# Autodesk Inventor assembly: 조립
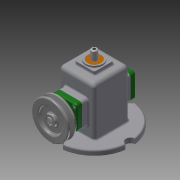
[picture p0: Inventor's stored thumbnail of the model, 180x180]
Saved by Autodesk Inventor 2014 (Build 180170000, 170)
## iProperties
Created: 2018-07
Part Number: 조립
Document SubType Name: Assembly
Designer: kh
Author: kh
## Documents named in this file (16)
- C:\Users\kh\Desktop\480707V1023\조립.iam
- C:\Users\kh\Desktop\480707V1023\본체.ipt
- C:\Users\kh\Desktop\480707V1023\V벨트풀리.ipt
- C:\Users\kh\Desktop\480707V1023\고정핀 1.2x8.ipt
- C:\Users\kh\Desktop\480707V1023\뒤커버.ipt
- C:\Users\kh\Desktop\480707V1023\링크.ipt
- C:\Users\kh\Desktop\480707V1023\멈춤나사 M3x8.ipt
- C:\Users\kh\Desktop\480707V1023\베어링 12x32x10.ipt
- C:\Users\kh\Desktop\480707V1023\볼트 M4.ipt
- C:\Users\kh\Desktop\480707V1023\부시.ipt
- C:\Users\kh\Desktop\480707V1023\슬라이드.ipt
- C:\Users\kh\Desktop\480707V1023\앞커버.ipt
- C:\Users\kh\Desktop\480707V1023\오일 실 12 25 7.ipt
- C:\Users\kh\Desktop\480707V1023\키 4x4x10.ipt
- C:\Users\kh\Desktop\480707V1023\편심축.ipt
- C:\Users\kh\Desktop\480707V1023\핀 5x18.ipt
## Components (3 placed, 3 different names)
1. V벨트풀리:1 — Mate:21, Mate:25, Flush:1, Mate:26, Angle:1
2. 핀 5x18:1 — Mate:9, Mate:10, Mate:11, Mate:12
3. 고정핀 1.2x8:2 — Mate:12, Flush:2
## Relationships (10: Mate 7, Flush 2, Angle 1)
- Mate:9: 핀 5x18:1
- Mate:10: 핀 5x18:1
- Mate:11: 핀 5x18:1
- Mate:12: 핀 5x18:1 ↔ 고정핀 1.2x8:2
- Mate:21: V벨트풀리:1
- Mate:25: V벨트풀리:1
- Flush:1: V벨트풀리:1
- Mate:26: V벨트풀리:1
- Angle:1: V벨트풀리:1
- Flush:2: 고정핀 1.2x8:2
